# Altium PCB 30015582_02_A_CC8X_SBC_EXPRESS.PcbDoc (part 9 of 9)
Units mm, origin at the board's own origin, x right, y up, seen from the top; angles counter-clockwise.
Board outline 87 x 63 mm, 6 copper layers (Top Layer-L1, GND Plane-L2, Signal-L3, PWR/Signal-L4, GND Plane-L5, Bottom Layer-L6), stack 1.172 mm thick; 169 components, 171 nets, 693 pads, 391 vias.
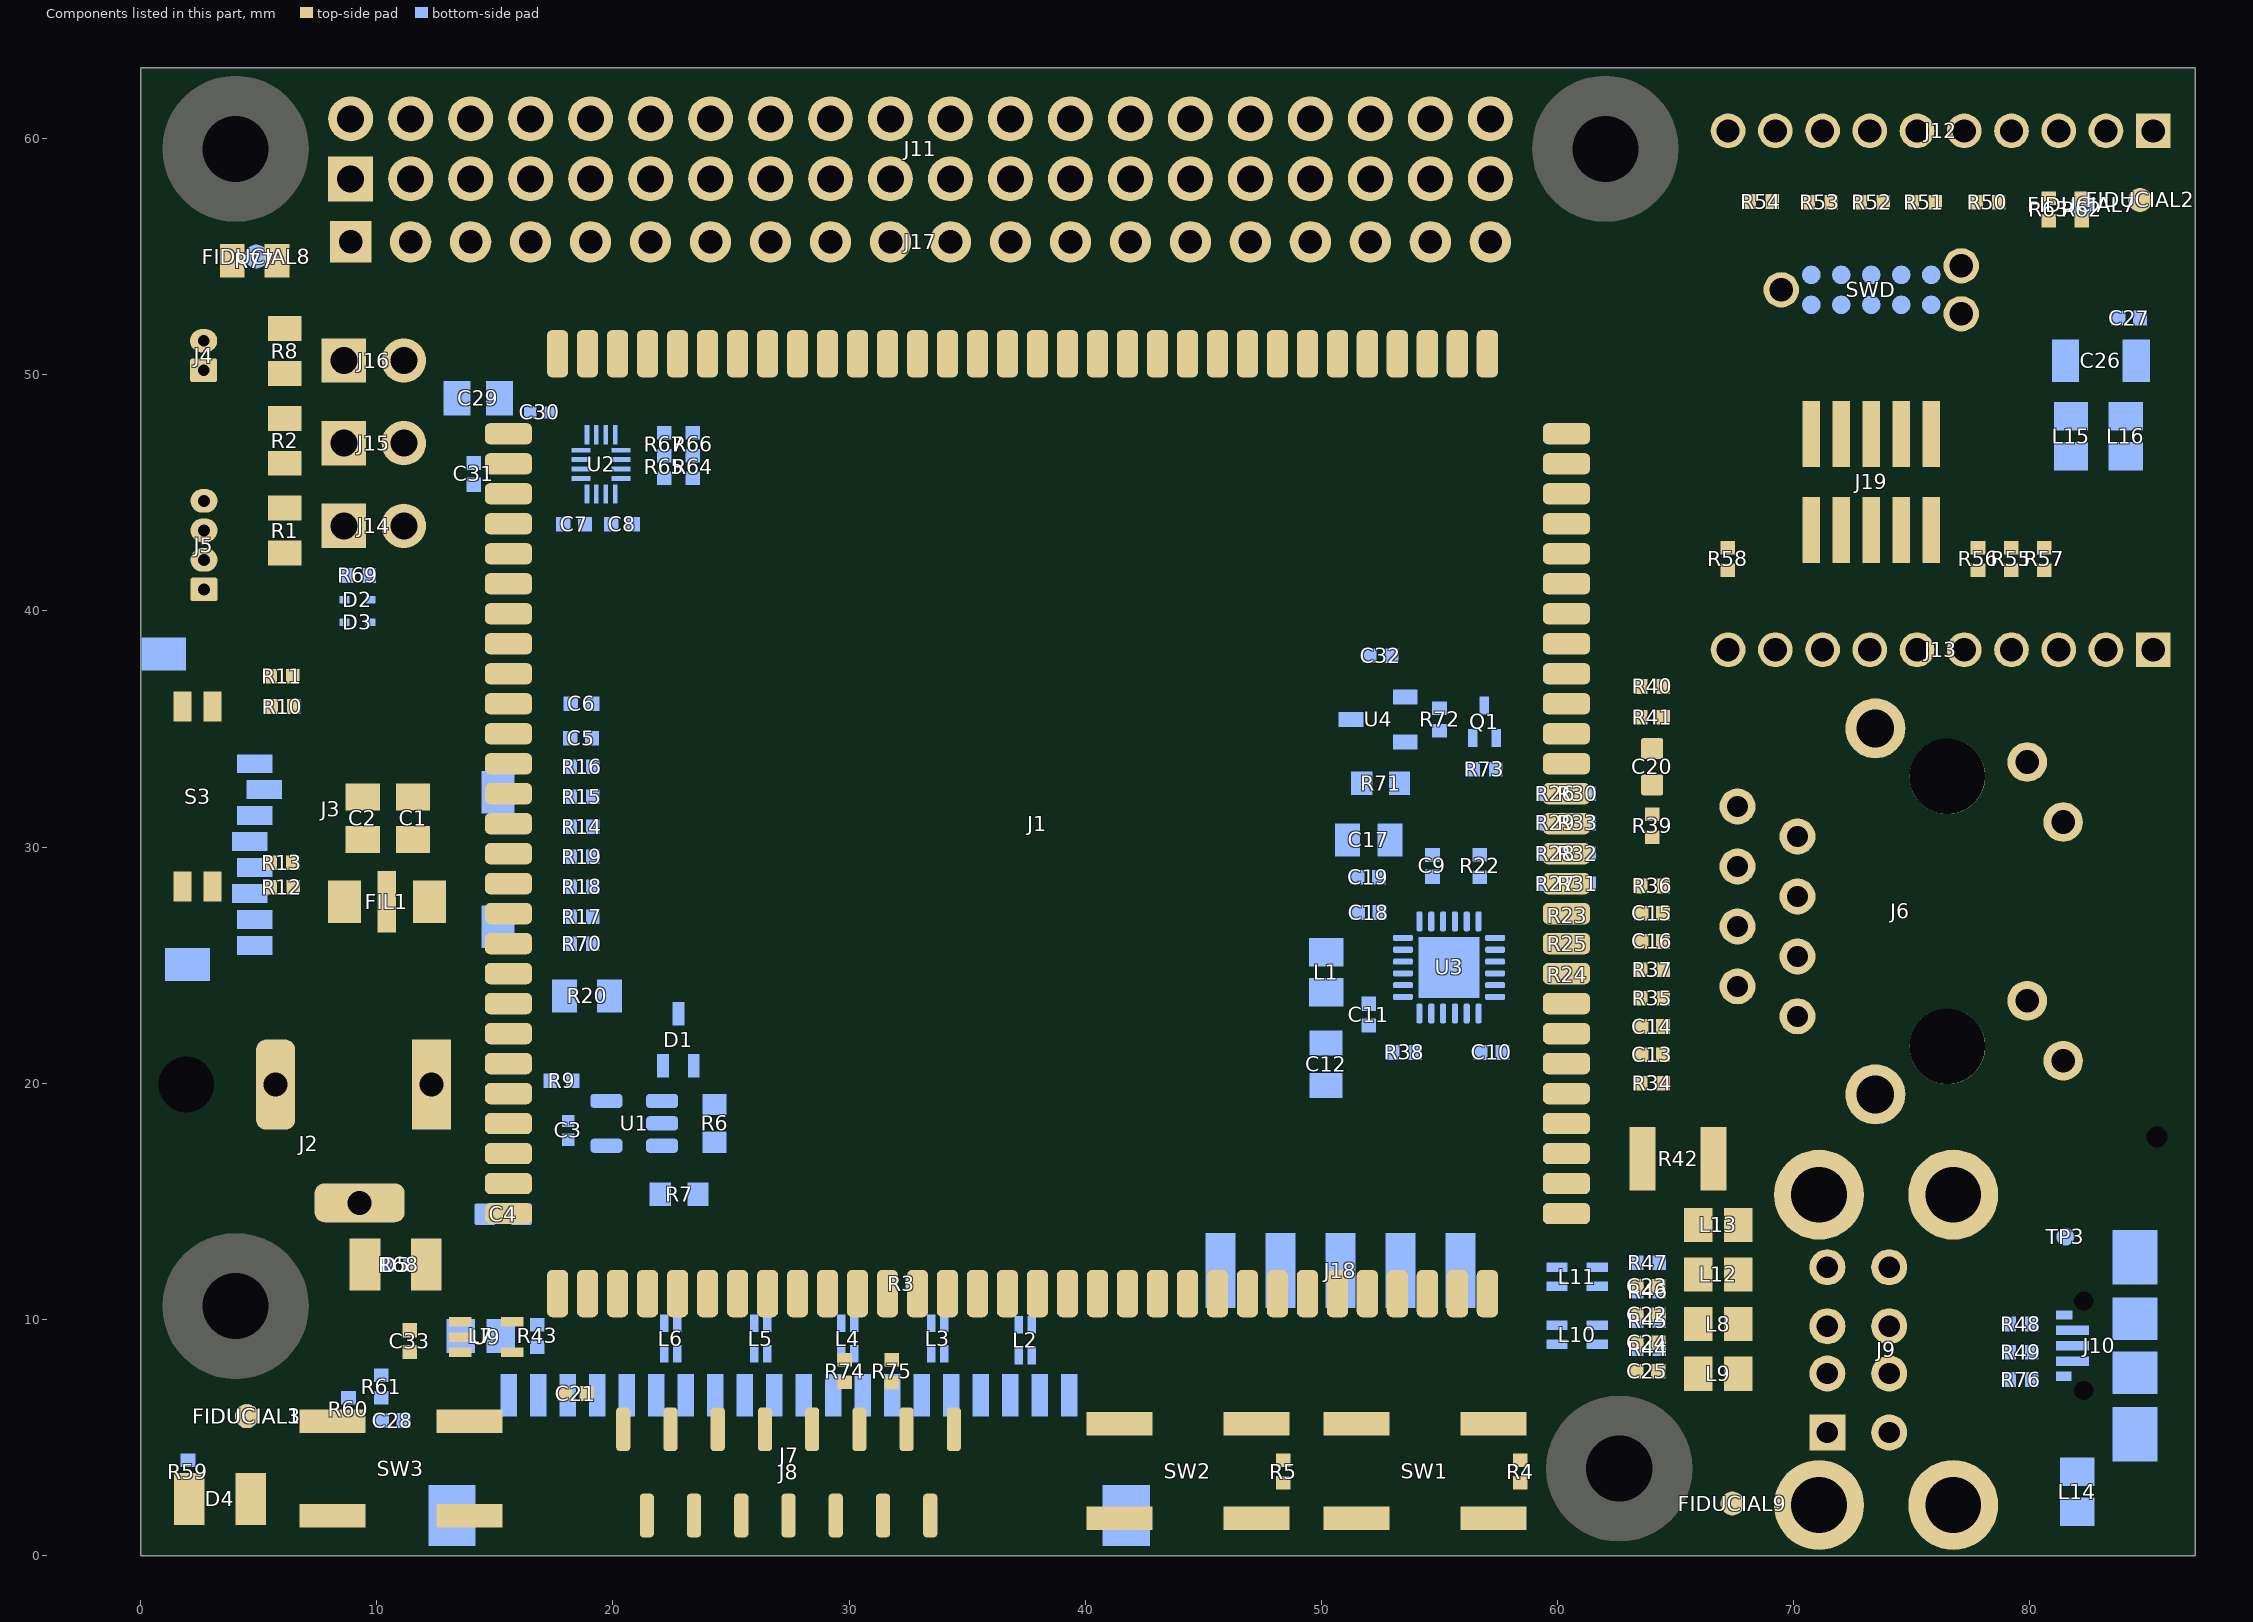
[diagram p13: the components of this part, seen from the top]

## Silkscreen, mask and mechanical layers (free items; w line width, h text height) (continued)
Resistive Material Bottom: (continued)
  text "u" at 198.406,163.593 h4.63
  text "t" at 200.433,163.593 h4.63
  text "r" at 202.629,163.593 h4.63
  text "e" at 203.938,163.593 h4.63
  text "d" at 205.88,163.593 h4.63
  text "u" at 207.907,163.593 h4.63
  text "c" at 209.933,163.593 h4.63
  text "i" at 211.58,163.593 h4.63
  text "n" at 212.467,163.593 h4.63
  text "g" at 214.494,163.593 h4.63
  text "t" at 217.196,163.593 h4.63
  text "h" at 218.505,163.593 h4.63
  text "i" at 220.532,163.593 h4.63
  text "s" at 221.419,163.593 h4.63
  text "c" at 223.826,163.593 h4.63
  text "l" at 225.472,163.593 h4.63
  text "e" at 226.359,163.593 h4.63
  text "a" at 228.301,163.593 h4.63
  text "r" at 230.159,163.593 h4.63
  text "a" at 231.511,163.593 h4.63
  text "n" at 233.369,163.593 h4.63
  text "c" at 235.395,163.593 h4.63
  text "e" at 237,163.593 h4.63
  text "l" at 85.2,158.864 h4.63
  text "o" at 86.087,158.864 h4.63
  text "c" at 88.156,158.864 h4.63
  text "a" at 89.803,158.864 h4.63
  text "l" at 91.66,158.864 h4.63
  text "l" at 92.547,158.864 h4.63
  text "y" at 93.434,158.864 h4.63
  text "." at 95.207,158.864 h4.63
  text "T" at 85.2,149.405 h4.63
  text "h" at 87.1,149.405 h4.63
  text "a" at 89.127,149.405 h4.63
  text "n" at 90.985,149.405 h4.63
  text "k" at 93.012,149.405 h4.63
  text "s" at 94.785,149.405 h4.63
  text "," at 96.305,149.405 h4.63
  text "S" at 85.2,144.676 h4.63
  text "é" at 86.973,144.676 h4.63
  text "b" at 88.916,144.676 h4.63
  text "a" at 90.943,144.676 h4.63
  text "s" at 92.801,144.676 h4.63
  text "t" at 94.321,144.676 h4.63
  text "i" at 95.63,144.676 h4.63
  text "e" at 96.516,144.676 h4.63
  text "n" at 98.459,144.676 h4.63
  text "F" at 85.2,135.26 h4.63
  text "r" at 86.973,135.26 h4.63
  text "o" at 88.367,135.26 h4.63
  text "m" at 90.436,135.26 h4.63
  text ":" at 93.603,135.26 h4.63
  text "J" at 95.594,135.26 h4.63
  text "o" at 96.819,135.26 h4.63
  text "s" at 98.888,135.26 h4.63
  text "e" at 100.408,135.26 h4.63
  text "E" at 103.195,135.26 h4.63
  text "n" at 105.095,135.26 h4.63
  text "r" at 107.122,135.26 h4.63
  text "i" at 108.473,135.26 h4.63
  text "q" at 109.36,135.26 h4.63
  text "u" at 111.387,135.26 h4.63
  text "e" at 113.414,135.26 h4.63
  text "C" at 116.243,135.26 h4.63
  text "a" at 118.312,135.26 h4.63
  text "s" at 120.17,135.26 h4.63
  text "t" at 121.647,135.26 h4.63
  text "e" at 122.956,135.26 h4.63
  text "l" at 124.899,135.26 h4.63
  text "l" at 125.786,135.26 h4.63
  text "[" at 127.517,135.26 h4.63
  text "m" at 128.857,135.26 h4.63
  text "a" at 131.981,135.26 h4.63
  text "i" at 133.839,135.26 h4.63
  text "l" at 134.726,135.26 h4.63
  text "t" at 135.613,135.26 h4.63
  text "o" at 136.88,135.26 h4.63
  text ":" at 138.949,135.26 h4.63
  text "e" at 140.004,135.26 h4.63
  text "n" at 141.947,135.26 h4.63
  text "r" at 143.973,135.26 h4.63
  text "i" at 145.325,135.26 h4.63
  text "q" at 146.211,135.26 h4.63
  text "u" at 148.238,135.26 h4.63
  text "e" at 150.265,135.26 h4.63
  text "@" at 152.207,135.26 h4.63
  text "c" at 155.628,135.26 h4.63
  text "i" at 157.274,135.26 h4.63
  text "d" at 158.161,135.26 h4.63
  text "e" at 160.188,135.26 h4.63
  text "i" at 162.13,135.26 h4.63
  text "n" at 163.017,135.26 h4.63
  text "." at 165.044,135.26 h4.63
  text "c" at 166.015,135.26 h4.63
  text "o" at 167.662,135.26 h4.63
  text "m" at 169.689,135.26 h4.63
  text "]" at 173.023,135.26 h4.63
  text "S" at 85.2,130.531 h4.63
  text "e" at 87.016,130.531 h4.63
  text "n" at 88.958,130.531 h4.63
  text "t" at 91.027,130.531 h4.63
  text ":" at 92.378,130.531 h4.63
  text "T" at 94.364,130.531 h4.63
  text "u" at 96.264,130.531 h4.63
  text "e" at 98.291,130.531 h4.63
  text "s" at 100.233,130.531 h4.63
  text "d" at 101.754,130.531 h4.63
  text "a" at 103.78,130.531 h4.63
  text "y" at 105.638,130.531 h4.63
  text "," at 107.412,130.531 h4.63
  text "J" at 109.27,130.531 h4.63
  text "a" at 110.494,130.531 h4.63
  text "n" at 112.352,130.531 h4.63
  text "u" at 114.379,130.531 h4.63
  text "a" at 116.406,130.531 h4.63
  text "r" at 118.377,130.531 h4.63
  text "y" at 119.729,130.531 h4.63
  text "1" at 122.347,130.531 h4.63
  text "6" at 124.289,130.531 h4.63
  text "," at 126.274,130.531 h4.63
  text "2" at 128.089,130.531 h4.63
  text "0" at 130.074,130.531 h4.63
  text "1" at 132.016,130.531 h4.63
  text "8" at 134.001,130.531 h4.63
  text "9" at 136.83,130.531 h4.63
  text ":" at 138.814,130.531 h4.63
  text "0" at 139.828,130.531 h4.63
  text "9" at 141.812,130.531 h4.63
  text "A" at 144.642,130.531 h4.63
  text "M" at 146.879,130.531 h4.63
  text "T" at 85.2,125.801 h4.63
  text "o" at 87.142,125.801 h4.63
  text ":" at 89.211,125.801 h4.63
  text "M" at 91.182,125.801 h4.63
  text "e" at 94.518,125.801 h4.63
  text "y" at 96.418,125.801 h4.63
  text "e" at 98.192,125.801 h4.63
  text "r" at 100.134,125.801 h4.63
  text "," at 101.485,125.801 h4.63
  text "S" at 103.301,125.801 h4.63
  text "e" at 105.074,125.801 h4.63
  text "b" at 107.017,125.801 h4.63
  text "a" at 109.043,125.801 h4.63
  text "s" at 110.901,125.801 h4.63
  text "t" at 112.421,125.801 h4.63
  text "i" at 113.73,125.801 h4.63
  text "e" at 114.575,125.801 h4.63
  text "n" at 116.517,125.801 h4.63
  text "<" at 119.431,125.801 h4.63
  text "S" at 121.517,125.801 h4.63
  text "e" at 123.29,125.801 h4.63
  text "b" at 125.233,125.801 h4.63
  text "a" at 127.217,125.801 h4.63
  text "s" at 129.075,125.801 h4.63
  text "t" at 130.595,125.801 h4.63
  text "i" at 131.904,125.801 h4.63
  text "e" at 132.791,125.801 h4.63
  text "n" at 134.733,125.801 h4.63
  text "." at 136.76,125.801 h4.63
  text "M" at 137.731,125.801 h4.63
  text "e" at 141.025,125.801 h4.63
  text "y" at 142.967,125.801 h4.63
  text "e" at 144.741,125.801 h4.63
  text "r" at 146.641,125.801 h4.63
  text "@" at 147.992,125.801 h4.63
  text "d" at 151.455,125.801 h4.63
  text "i" at 153.482,125.801 h4.63
  text "g" at 154.368,125.801 h4.63
  text "i" at 156.184,125.801 h4.63
  text "." at 157.071,125.801 h4.63
  text "c" at 158.042,125.801 h4.63
  text "o" at 159.689,125.801 h4.63
  text "m" at 161.715,125.801 h4.63
  text ">" at 165.046,125.801 h4.63
  text "C" at 85.2,121.072 h4.63
  text "c" at 87.269,121.072 h4.63
  text ":" at 88.916,121.072 h4.63
  text "A" at 90.885,121.072 h4.63
  text "n" at 93.123,121.072 h4.63
  text "z" at 95.15,121.072 h4.63
  text "o" at 96.67,121.072 h4.63
  text "l" at 98.739,121.072 h4.63
  text "a" at 99.626,121.072 h4.63
  text "," at 101.441,121.072 h4.63
  text "J" at 103.299,121.072 h4.63
  text "u" at 104.524,121.072 h4.63
  text "a" at 106.551,121.072 h4.63
  text "n" at 108.409,121.072 h4.63
  text "<" at 111.322,121.072 h4.63
  text "J" at 113.371,121.072 h4.63
  text "u" at 114.596,121.072 h4.63
  text "a" at 116.622,121.072 h4.63
  text "n" at 118.48,121.072 h4.63
  text "." at 120.507,121.072 h4.63
  text "A" at 121.478,121.072 h4.63
  text "n" at 123.716,121.072 h4.63
  text "z" at 125.743,121.072 h4.63
  text "o" at 127.263,121.072 h4.63
  text "l" at 129.332,121.072 h4.63
  text "a" at 130.219,121.072 h4.63
  text "@" at 132.077,121.072 h4.63
  text "d" at 135.539,121.072 h4.63
  text "i" at 137.566,121.072 h4.63
  text "g" at 138.453,121.072 h4.63
  text "i" at 140.269,121.072 h4.63
  text "." at 141.155,121.072 h4.63
  text "c" at 142.127,121.072 h4.63
  text "o" at 143.773,121.072 h4.63
  text "m" at 145.8,121.072 h4.63
  text ">" at 149.094,121.072 h4.63
  text ";" at 150.994,121.072 h4.63
  text "P" at 152.894,121.072 h4.63
  text "e" at 154.921,121.072 h4.63
  text "r" at 156.864,121.072 h4.63
  text "e" at 158.215,121.072 h4.63
  text "z" at 160.157,121.072 h4.63
  text "," at 161.677,121.072 h4.63
  text "P" at 163.493,121.072 h4.63
  text "e" at 165.478,121.072 h4.63
  text "d" at 167.42,121.072 h4.63
  text "r" at 169.447,121.072 h4.63
  text "o" at 170.798,121.072 h4.63
  text "<" at 173.754,121.072 h4.63
  text "P" at 175.78,121.072 h4.63
  text "e" at 177.807,121.072 h4.63
  text "d" at 179.749,121.072 h4.63
  text "r" at 181.776,121.072 h4.63
  text "o" at 183.085,121.072 h4.63
  text "." at 185.154,121.072 h4.63
  text "P" at 186.125,121.072 h4.63
  text "e" at 188.11,121.072 h4.63
  text "r" at 190.052,121.072 h4.63
  text "e" at 191.404,121.072 h4.63
  text "z" at 193.346,121.072 h4.63
  text "@" at 194.866,121.072 h4.63
  text "d" at 198.329,121.072 h4.63
  text "i" at 200.355,121.072 h4.63
  text "g" at 201.242,121.072 h4.63
  text "i" at 203.058,121.072 h4.63
  text "." at 203.945,121.072 h4.63
  text "c" at 204.916,121.072 h4.63
  text "o" at 206.563,121.072 h4.63
  text "m" at 208.589,121.072 h4.63
  text ">" at 211.843,121.072 h4.63
  text "S" at 85.2,116.343 h4.63
  text "u" at 87.016,116.343 h4.63
  text "b" at 89.085,116.343 h4.63
  text "j" at 91.154,116.343 h4.63
  text "e" at 92.167,116.343 h4.63
  text "c" at 94.11,116.343 h4.63
  text "t" at 95.756,116.343 h4.63
  text ":" at 97.108,116.343 h4.63
  text "R" at 99.116,116.343 h4.63
  text "E" at 101.227,116.343 h4.63
  text ":" at 103.127,116.343 h4.63
  text "C" at 105.027,116.343 h4.63
  text "C" at 107.096,116.343 h4.63
  text "8" at 109.123,116.343 h4.63
  text "X" at 111.108,116.343 h4.63
  text "_" at 113.135,116.343 h4.63
  text "S" at 115.077,116.343 h4.63
  text "B" at 116.85,116.343 h4.63
  text "C" at 118.962,116.343 h4.63
  text "_" at 120.989,116.343 h4.63
  text "E" at 122.931,116.343 h4.63
  text "X" at 124.831,116.343 h4.63
  text "P" at 126.816,116.343 h4.63
  text "R" at 128.842,116.343 h4.63
  text "E" at 130.954,116.343 h4.63
  text "S" at 132.854,116.343 h4.63
  text "S" at 134.627,116.343 h4.63
  text "H" at 85.2,106.884 h4.63
  text "i" at 87.607,106.884 h4.63
  text "S" at 89.38,106.884 h4.63
  text "e" at 91.154,106.884 h4.63
  text "b" at 93.096,106.884 h4.63
  text "a" at 95.123,106.884 h4.63
  text "s" at 96.981,106.884 h4.63
  text "t" at 98.501,106.884 h4.63
  text "i" at 99.81,106.884 h4.63
  text "e" at 100.697,106.884 h4.63
  text "n" at 102.639,106.884 h4.63
  text "," at 104.666,106.884 h4.63
  text "A" at 85.2,97.426 h4.63
  text "s" at 87.438,97.426 h4.63
  text "y" at 89.845,97.426 h4.63
  text "o" at 91.576,97.426 h4.63
  text "u" at 93.645,97.426 h4.63
  text "c" at 96.559,97.426 h4.63
  text "a" at 98.205,97.426 h4.63
  text "n" at 100.063,97.426 h4.63
  text "s" at 102.977,97.426 h4.63
  text "e" at 104.455,97.426 h4.63
  text "e" at 106.397,97.426 h4.63
  text "i" at 109.226,97.426 h4.63
  text "n" at 110.113,97.426 h4.63
  text "t" at 112.984,97.426 h4.63
  text "h" at 114.293,97.426 h4.63
  text "e" at 116.32,97.426 h4.63
  text "i" at 119.149,97.426 h4.63
  text "m" at 119.994,97.426 h4.63
  text "a" at 123.118,97.426 h4.63
  text "g" at 124.976,97.426 h4.63
  text "e" at 126.75,97.426 h4.63
  text "b" at 129.579,97.426 h4.63
  text "e" at 131.606,97.426 h4.63
  text "l" at 133.548,97.426 h4.63
  text "o" at 134.392,97.426 h4.63
  text "w" at 136.461,97.426 h4.63
  text "," at 139.248,97.426 h4.63
  text "t" at 141.064,97.426 h4.63
  text "h" at 142.373,97.426 h4.63
  text "e" at 144.4,97.426 h4.63
  text "g" at 147.229,97.426 h4.63
  text "r" at 149.045,97.426 h4.63
  text "e" at 150.396,97.426 h4.63
  text "e" at 152.296,97.426 h4.63
  text "n" at 154.238,97.426 h4.63
  text "a" at 157.152,97.426 h4.63
  text "r" at 159.01,97.426 h4.63
  text "e" at 160.361,97.426 h4.63
  text "a" at 162.261,97.426 h4.63
  text "i" at 165.006,97.426 h4.63
  text "s" at 165.893,97.426 h4.63
  text "t" at 168.299,97.426 h4.63
  text "h" at 169.566,97.426 h4.63
  text "e" at 171.593,97.426 h4.63
  text "a" at 174.422,97.426 h4.63
  text "f" at 176.28,97.426 h4.63
  text "f" at 177.462,97.426 h4.63
  text "e" at 178.645,97.426 h4.63
  text "c" at 180.587,97.426 h4.63
  text "t" at 182.191,97.426 h4.63
  text "e" at 183.5,97.426 h4.63
  text "d" at 185.443,97.426 h4.63
  text "a" at 188.356,97.426 h4.63
  text "r" at 190.214,97.426 h4.63
  text "e" at 191.523,97.426 h4.63
  text "a" at 193.466,97.426 h4.63
  text "." at 195.324,97.426 h4.63
  text "" at 85.2,92.739 h4.63
  text "D" at 86.889,92.739 h4.63
  text "i" at 89.338,92.739 h4.63
  text "s" at 90.309,92.739 h4.63
  text "t" at 91.872,92.739 h4.63
  text "a" at 93.223,92.739 h4.63
  text "n" at 95.123,92.739 h4.63
  text "c" at 97.15,92.739 h4.63
  text "e" at 98.797,92.739 h4.63
  text "i" at 101.626,92.739 h4.63
  text "s" at 102.555,92.739 h4.63
  text "m" at 105.004,92.739 h4.63
  text "e" at 108.171,92.739 h4.63
  text "a" at 110.113,92.739 h4.63
  text "s" at 112.013,92.739 h4.63
  text "u" at 113.575,92.739 h4.63
  text "r" at 115.602,92.739 h4.63
  text "e" at 116.996,92.739 h4.63
  text "d" at 118.938,92.739 h4.63
  text "f" at 121.894,92.739 h4.63
  text "r" at 123.118,92.739 h4.63
  text "o" at 124.512,92.739 h4.63
  text "m" at 126.539,92.739 h4.63
  text "t" at 130.592,92.739 h4.63
  text "h" at 131.943,92.739 h4.63
  text "e" at 134.012,92.739 h4.63
  text "e" at 136.842,92.739 h4.63
  text "d" at 138.784,92.739 h4.63
  text "g" at 140.853,92.739 h4.63
  text "e" at 142.711,92.739 h4.63
  text "t" at 145.54,92.739 h4.63
  text "h" at 146.891,92.739 h4.63
  text "e" at 148.96,92.739 h4.63
  text "a" at 151.789,92.739 h4.63
  text "n" at 153.689,92.739 h4.63
  text "n" at 155.758,92.739 h4.63
  text "u" at 157.827,92.739 h4.63
  text "l" at 159.897,92.739 h4.63
  text "a" at 160.868,92.739 h4.63
  text "r" at 162.768,92.739 h4.63
  text "r" at 165.006,92.739 h4.63
  text "i" at 166.399,92.739 h4.63
  text "n" at 167.37,92.739 h4.63
  text "g" at 169.397,92.739 h4.63
  text "o" at 172.142,92.739 h4.63
  text "f" at 174.211,92.739 h4.63
  text "a" at 176.322,92.739 h4.63
  text "P" at 179.109,92.739 h4.63
  text "T" at 181.136,92.739 h4.63
  text "H" at 183.078,92.739 h4.63
  text "l" at 186.372,92.739 h4.63
  text "e" at 187.343,92.739 h4.63
  text "a" at 189.285,92.739 h4.63
  text "d" at 191.185,92.739 h4.63
  text "t" at 194.141,92.739 h4.63
  text "o" at 195.492,92.739 h4.63
  text "t" at 198.448,92.739 h4.63
  text "h" at 199.799,92.739 h4.63
  text "e" at 201.868,92.739 h4.63
  text "n" at 204.698,92.739 h4.63
  text "e" at 206.767,92.739 h4.63
  text "a" at 208.709,92.739 h4.63
  text "r" at 210.609,92.739 h4.63
  text "e" at 212.003,92.739 h4.63
  text "s" at 213.945,92.739 h4.63
  text "t" at 215.507,92.739 h4.63
  text "S" at 217.745,92.739 h4.63
  text "M" at 219.561,92.739 h4.63
  text "T" at 222.939,92.739 h4.63
  text "p" at 85.2,88.01 h4.63
  text "a" at 87.269,88.01 h4.63
  text "d" at 89.169,88.01 h4.63
  text "." at 91.238,88.01 h4.63
  text "T" at 94.11,88.01 h4.63
  text "h" at 96.052,88.01 h4.63
  text "i" at 98.121,88.01 h4.63
  text "s" at 99.05,88.01 h4.63
  text "d" at 101.499,88.01 h4.63
  text "i" at 103.568,88.01 h4.63
  text "s" at 104.497,88.01 h4.63
  text "t" at 106.059,88.01 h4.63
  text "a" at 107.411,88.01 h4.63
  text "n" at 109.311,88.01 h4.63
  text "c" at 111.38,88.01 h4.63
  text "e" at 113.026,88.01 h4.63
  text "n" at 115.856,88.01 h4.63
  text "e" at 117.925,88.01 h4.63
  text "e" at 119.867,88.01 h4.63
  text "d" at 121.809,88.01 h4.63
  text "s" at 123.878,88.01 h4.63
  text "t" at 126.285,88.01 h4.63
  text "o" at 127.754,88.01 h4.63
  text "b" at 130.709,88.01 h4.63
  text "e" at 132.778,88.01 h4.63
  text "m" at 135.608,88.01 h4.63
  text "i" at 138.774,88.01 h4.63
  text "n" at 139.746,88.01 h4.63
  text "i" at 141.815,88.01 h4.63
  text "m" at 142.744,88.01 h4.63
  text "u" at 145.911,88.01 h4.63
  text "m" at 147.98,88.01 h4.63
  text "5" at 151.991,88.01 h4.63
  text "." at 153.976,88.01 h4.63
  text "0" at 154.989,88.01 h4.63
  text "m" at 156.974,88.01 h4.63
  text "m" at 160.14,88.01 h4.63
  text "." at 163.265,88.01 h4.63
  text "T" at 166.234,88.01 h4.63
  text "h" at 168.177,88.01 h4.63
  text "i" at 170.204,88.01 h4.63
  text "s" at 171.175,88.01 h4.63
  text "i" at 173.582,88.01 h4.63
  text "s" at 174.553,88.01 h4.63
  text "t" at 176.96,88.01 h4.63
  text "h" at 178.311,88.01 h4.63
  text "e" at 180.38,88.01 h4.63
  text "s" at 183.209,88.01 h4.63
  text "a" at 184.771,88.01 h4.63
  text "m" at 186.671,88.01 h4.63
  text "e" at 189.838,88.01 h4.63
  text "f" at 192.667,88.01 h4.63
  text "o" at 193.892,88.01 h4.63
  text "r" at 195.961,88.01 h4.63
  text "w" at 198.199,88.01 h4.63
  text "a" at 201.112,88.01 h4.63
  text "v" at 202.97,88.01 h4.63
  text "e" at 204.828,88.01 h4.63
  text "o" at 207.657,88.01 h4.63
  text "r" at 209.726,88.01 h4.63
  text "s" at 211.964,88.01 h4.63
  text "e" at 213.527,88.01 h4.63
  text "l" at 215.469,88.01 h4.63
  text "e" at 216.44,88.01 h4.63
  text "c" at 218.383,88.01 h4.63
  text "t" at 220.029,88.01 h4.63
  text "i" at 221.338,88.01 h4.63
  text "v" at 222.267,88.01 h4.63
  text "e" at 224.125,88.01 h4.63
  text "s" at 226.954,88.01 h4.63
  text "o" at 228.517,88.01 h4.63
  text "l" at 230.586,88.01 h4.63
  text "d" at 231.557,88.01 h4.63
  text "e" at 233.626,88.01 h4.63
  text "r" at 235.568,88.01 h4.63
  text "." at 236.919,88.01 h4.63
  text "" at 239.208,88.01 h4.63
  text "I" at 85.2,78.551 h4.63
  text "t" at 87.058,78.551 h4.63
  text "h" at 88.367,78.551 h4.63
  text "i" at 90.394,78.551 h4.63
  text "n" at 91.28,78.551 h4.63
  text "k" at 93.307,78.551 h4.63
  text "w" at 95.967,78.551 h4.63
  text "e" at 98.712,78.551 h4.63
  text "c" at 101.541,78.551 h4.63
  text "a" at 103.188,78.551 h4.63
  text "n" at 105.046,78.551 h4.63
  text "n" at 107.073,78.551 h4.63
  text "o" at 109.1,78.551 h4.63
  text "t" at 111.126,78.551 h4.63
  text "d" at 113.322,78.551 h4.63
  text "o" at 115.307,78.551 h4.63
  text "a" at 118.262,78.551 h4.63
  text "n" at 120.12,78.551 h4.63
  text "y" at 122.147,78.551 h4.63
  text "t" at 123.878,78.551 h4.63
  text "h" at 125.187,78.551 h4.63
  text "i" at 127.214,78.551 h4.63
  text "n" at 128.101,78.551 h4.63
  text "g" at 130.128,78.551 h4.63
  text "w" at 132.83,78.551 h4.63
  text "i" at 135.617,78.551 h4.63
  text "t" at 136.504,78.551 h4.63
  text "h" at 137.813,78.551 h4.63
  text "o" at 139.84,78.551 h4.63
  text "u" at 141.909,78.551 h4.63
  text "t" at 143.935,78.551 h4.63
  text "y" at 146.089,78.551 h4.63
  text "o" at 147.82,78.551 h4.63
  text "u" at 149.889,78.551 h4.63
  text "r" at 151.916,78.551 h4.63
  text "o" at 154.112,78.551 h4.63
  text "p" at 156.181,78.551 h4.63
  text "i" at 158.208,78.551 h4.63
  text "n" at 159.094,78.551 h4.63
  text "i" at 161.121,78.551 h4.63
  text "o" at 162.008,78.551 h4.63
  text "n" at 164.077,78.551 h4.63
  text "," at 166.104,78.551 h4.63
  text "m" at 167.919,78.551 h4.63
  text "o" at 171.002,78.551 h4.63
  text "s" at 173.071,78.551 h4.63
  text "t" at 174.591,78.551 h4.63
  text "o" at 176.744,78.551 h4.63
  text "f" at 178.813,78.551 h4.63
  text "t" at 180.84,78.551 h4.63
  text "h" at 182.149,78.551 h4.63
  text "e" at 184.176,78.551 h4.63
  text "s" at 186.118,78.551 h4.63
  text "e" at 187.639,78.551 h4.63
  text "c" at 190.425,78.551 h4.63
  text "o" at 192.03,78.551 h4.63
  text "m" at 194.099,78.551 h4.63
  text "p" at 197.224,78.551 h4.63
  text "o" at 199.208,78.551 h4.63
  text "n" at 201.277,78.551 h4.63
  text "e" at 203.304,78.551 h4.63
  text "n" at 205.246,78.551 h4.63
  text "t" at 207.273,78.551 h4.63
  text "s" at 208.582,78.551 h4.63
  text "w" at 210.947,78.551 h4.63
  text "e" at 213.692,78.551 h4.63
  text "h" at 216.521,78.551 h4.63
  text "a" at 218.547,78.551 h4.63
  text "v" at 220.405,78.551 h4.63
  text "e" at 222.137,78.551 h4.63
  text "t" at 224.966,78.551 h4.63
  text "o" at 226.232,78.551 h4.63
  text "k" at 229.188,78.551 h4.63
  text "e" at 230.919,78.551 h4.63
  text "p" at 232.862,78.551 h4.63
  text "t" at 234.889,78.551 h4.63
  text "a" at 85.2,73.822 h4.63
  text "w" at 87.058,73.822 h4.63
  text "a" at 89.845,73.822 h4.63
  text "y" at 91.703,73.822 h4.63
  text "f" at 94.363,73.822 h4.63
  text "r" at 95.545,73.822 h4.63
  text "o" at 96.854,73.822 h4.63
  text "m" at 98.881,73.822 h4.63
  text "P" at 102.85,73.822 h4.63
  text "T" at 104.877,73.822 h4.63
  text "H" at 106.777,73.822 h4.63
  text "l" at 110.071,73.822 h4.63
  text "e" at 110.915,73.822 h4.63
  text "a" at 112.858,73.822 h4.63
  text "d" at 114.715,73.822 h4.63
  text "h" at 117.629,73.822 h4.63
  text "a" at 119.656,73.822 h4.63
  text "v" at 121.514,73.822 h4.63
  text "e" at 123.245,73.822 h4.63
  text "t" at 126.074,73.822 h4.63
  text "o" at 127.341,73.822 h4.63
  text "b" at 130.297,73.822 h4.63
  text "e" at 132.323,73.822 h4.63
  text "c" at 135.11,73.822 h4.63
  text "l" at 136.757,73.822 h4.63
  text "o" at 137.644,73.822 h4.63
  text "s" at 139.713,73.822 h4.63
  text "e" at 141.191,73.822 h4.63
  text "t" at 144.02,73.822 h4.63
  text "h" at 145.329,73.822 h4.63
  text "e" at 147.313,73.822 h4.63
  text "c" at 150.142,73.822 h4.63
  text "o" at 151.747,73.822 h4.63
  text "m" at 153.774,73.822 h4.63
  text "p" at 156.899,73.822 h4.63
  text "o" at 158.925,73.822 h4.63
  text "n" at 160.994,73.822 h4.63
  text "e" at 163.021,73.822 h4.63
  text "n" at 164.964,73.822 h4.63
  text "t" at 166.99,73.822 h4.63
  text "," at 168.257,73.822 h4.63
  text "d" at 170.073,73.822 h4.63
  text "e" at 172.1,73.822 h4.63
  text "c" at 174.042,73.822 h4.63
  text "o" at 175.689,73.822 h4.63
  text "u" at 177.758,73.822 h4.63
  text "p" at 179.785,73.822 h4.63
  text "l" at 181.811,73.822 h4.63
  text "i" at 182.698,73.822 h4.63
  text "n" at 183.585,73.822 h4.63
  text "g" at 185.612,73.822 h4.63
  text "," at 187.427,73.822 h4.63
  text "d" at 189.285,73.822 h4.63
  text "i" at 191.312,73.822 h4.63
  text "f" at 192.199,73.822 h4.63
  text "f" at 193.381,73.822 h4.63
  text "e" at 194.563,73.822 h4.63
  text "r" at 196.506,73.822 h4.63
  text "e" at 197.857,73.822 h4.63
  text "n" at 199.799,73.822 h4.63
  text "t" at 201.784,73.822 h4.63
  text "i" at 203.093,73.822 h4.63
  text "a" at 203.98,73.822 h4.63
  text "l" at 205.838,73.822 h4.63
  text "p" at 207.611,73.822 h4.63
  text "a" at 209.638,73.822 h4.63
  text "i" at 211.496,73.822 h4.63
  text "r" at 212.34,73.822 h4.63
  text "s" at 213.692,73.822 h4.63
  text "," at 215.212,73.822 h4.63
  text "e" at 217.07,73.822 h4.63
  text "t" at 219.012,73.822 h4.63
  text "c" at 220.279,73.822 h4.63
  text "." at 221.925,73.822 h4.63
  text "." at 222.897,73.822 h4.63
  text "." at 223.868,73.822 h4.63
  text "E" at 226.395,73.822 h4.63
  text "v" at 228.295,73.822 h4.63
  text "e" at 230.026,73.822 h4.63
  text "n" at 231.969,73.822 h4.63
  text "t" at 234.882,73.822 h4.63
  text "h" at 236.191,73.822 h4.63
  text "e" at 238.218,73.822 h4.63
  text "m" at 85.2,69.093 h4.63
  text "i" at 88.325,69.093 h4.63
  text "c" at 89.211,69.093 h4.63
  text "r" at 90.858,69.093 h4.63
  text "o" at 92.167,69.093 h4.63
  text "S" at 94.236,69.093 h4.63
  text "D" at 96.01,69.093 h4.63
  text "C" at 99.261,69.093 h4.63
  text "A" at 101.33,69.093 h4.63
  text "R" at 103.568,69.093 h4.63
  text "D" at 105.679,69.093 h4.63
  text "i" at 108.931,69.093 h4.63
  text "s" at 109.817,69.093 h4.63
  text "a" at 112.224,69.093 h4.63
  text "f" at 114.082,69.093 h4.63
  text "f" at 115.264,69.093 h4.63
  text "e" at 116.447,69.093 h4.63
  text "c" at 118.347,69.093 h4.63
  text "t" at 119.994,69.093 h4.63
  text "e" at 121.303,69.093 h4.63
  text "d" at 123.245,69.093 h4.63
  text "." at 125.272,69.093 h4.63
  text "I" at 85.2,64.364 h4.63
  text "k" at 87.058,64.364 h4.63
  text "n" at 88.831,64.364 h4.63
  text "o" at 90.858,64.364 h4.63
  text "w" at 92.927,64.364 h4.63
  text "w" at 96.559,64.364 h4.63
  text "e" at 99.303,64.364 h4.63
  text "c" at 102.132,64.364 h4.63
  text "a" at 103.779,64.364 h4.63
  text "n" at 105.637,64.364 h4.63
  text "m" at 108.508,64.364 h4.63
  text "o" at 111.591,64.364 h4.63
  text "v" at 113.66,64.364 h4.63
  text "e" at 115.391,64.364 h4.63
  text "s" at 118.22,64.364 h4.63
  text "o" at 119.698,64.364 h4.63
  text "m" at 121.725,64.364 h4.63
  text "e" at 124.85,64.364 h4.63
  text "o" at 127.636,64.364 h4.63
  text "f" at 129.705,64.364 h4.63
  text "t" at 131.774,64.364 h4.63
  text "h" at 133.083,64.364 h4.63
  text "e" at 135.11,64.364 h4.63
  text "m" at 137.01,64.364 h4.63
  text "," at 140.135,64.364 h4.63
  text "b" at 141.951,64.364 h4.63
  text "u" at 143.978,64.364 h4.63
  text "t" at 146.004,64.364 h4.63
  text "I" at 148.2,64.364 h4.63
  text "d" at 150.058,64.364 h4.63
  text "o" at 152.043,64.364 h4.63
  text "n" at 154.998,64.364 h4.63
  text "o" at 157.025,64.364 h4.63
  text "t" at 159.052,64.364 h4.63
  text "k" at 161.248,64.364 h4.63
  text "n" at 163.021,64.364 h4.63
  text "o" at 165.006,64.364 h4.63
  text "w" at 167.075,64.364 h4.63
  text "w" at 170.706,64.364 h4.63
  text "h" at 173.493,64.364 h4.63
  text "e" at 175.52,64.364 h4.63
  text "t" at 177.462,64.364 h4.63
  text "h" at 178.771,64.364 h4.63
  text "e" at 180.798,64.364 h4.63
  text "r" at 182.74,64.364 h4.63
  text "c" at 184.936,64.364 h4.63
  text "o" at 186.583,64.364 h4.63
  text "n" at 188.652,64.364 h4.63
  text "n" at 190.679,64.364 h4.63
  text "e" at 192.706,64.364 h4.63
  text "c" at 194.606,64.364 h4.63
  text "t" at 196.253,64.364 h4.63
  text "o" at 197.519,64.364 h4.63
  text "r" at 199.588,64.364 h4.63
  text "s" at 200.94,64.364 h4.63
  text "o" at 203.304,64.364 h4.63
  text "r" at 205.373,64.364 h4.63
  text "m" at 207.569,64.364 h4.63
  text "i" at 210.694,64.364 h4.63
  text "c" at 211.58,64.364 h4.63
  text "r" at 213.185,64.364 h4.63
  text "o" at 214.536,64.364 h4.63
  text "S" at 216.605,64.364 h4.63
  text "D" at 218.379,64.364 h4.63
  text "c" at 221.63,64.364 h4.63
  text "a" at 223.277,64.364 h4.63
  text "n" at 225.135,64.364 h4.63
  text "b" at 228.048,64.364 h4.63
  text "e" at 230.075,64.364 h4.63
  text "m" at 85.2,59.634 h4.63
  text "o" at 88.325,59.634 h4.63
  text "v" at 90.351,59.634 h4.63
  text "e" at 92.125,59.634 h4.63
  text "d" at 94.067,59.634 h4.63
  text "." at 96.094,59.634 h4.63
Designers Notes:
  text "High Currents / VIN: 2A   INT. 60mils Ext 24mils / VSYS: 2A   / 3V3: 1.25A  INT: 35mils Ext 13mils / USB_Supply: 1A  INT: 24mils Ext 10mils" at -37.5,71.85 h1.52

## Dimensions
0,63 to 87,63 on Fab / Dimension
0,63 to 0,0 on Fab / Dimension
